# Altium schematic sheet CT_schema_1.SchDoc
size 385 x 337 mm
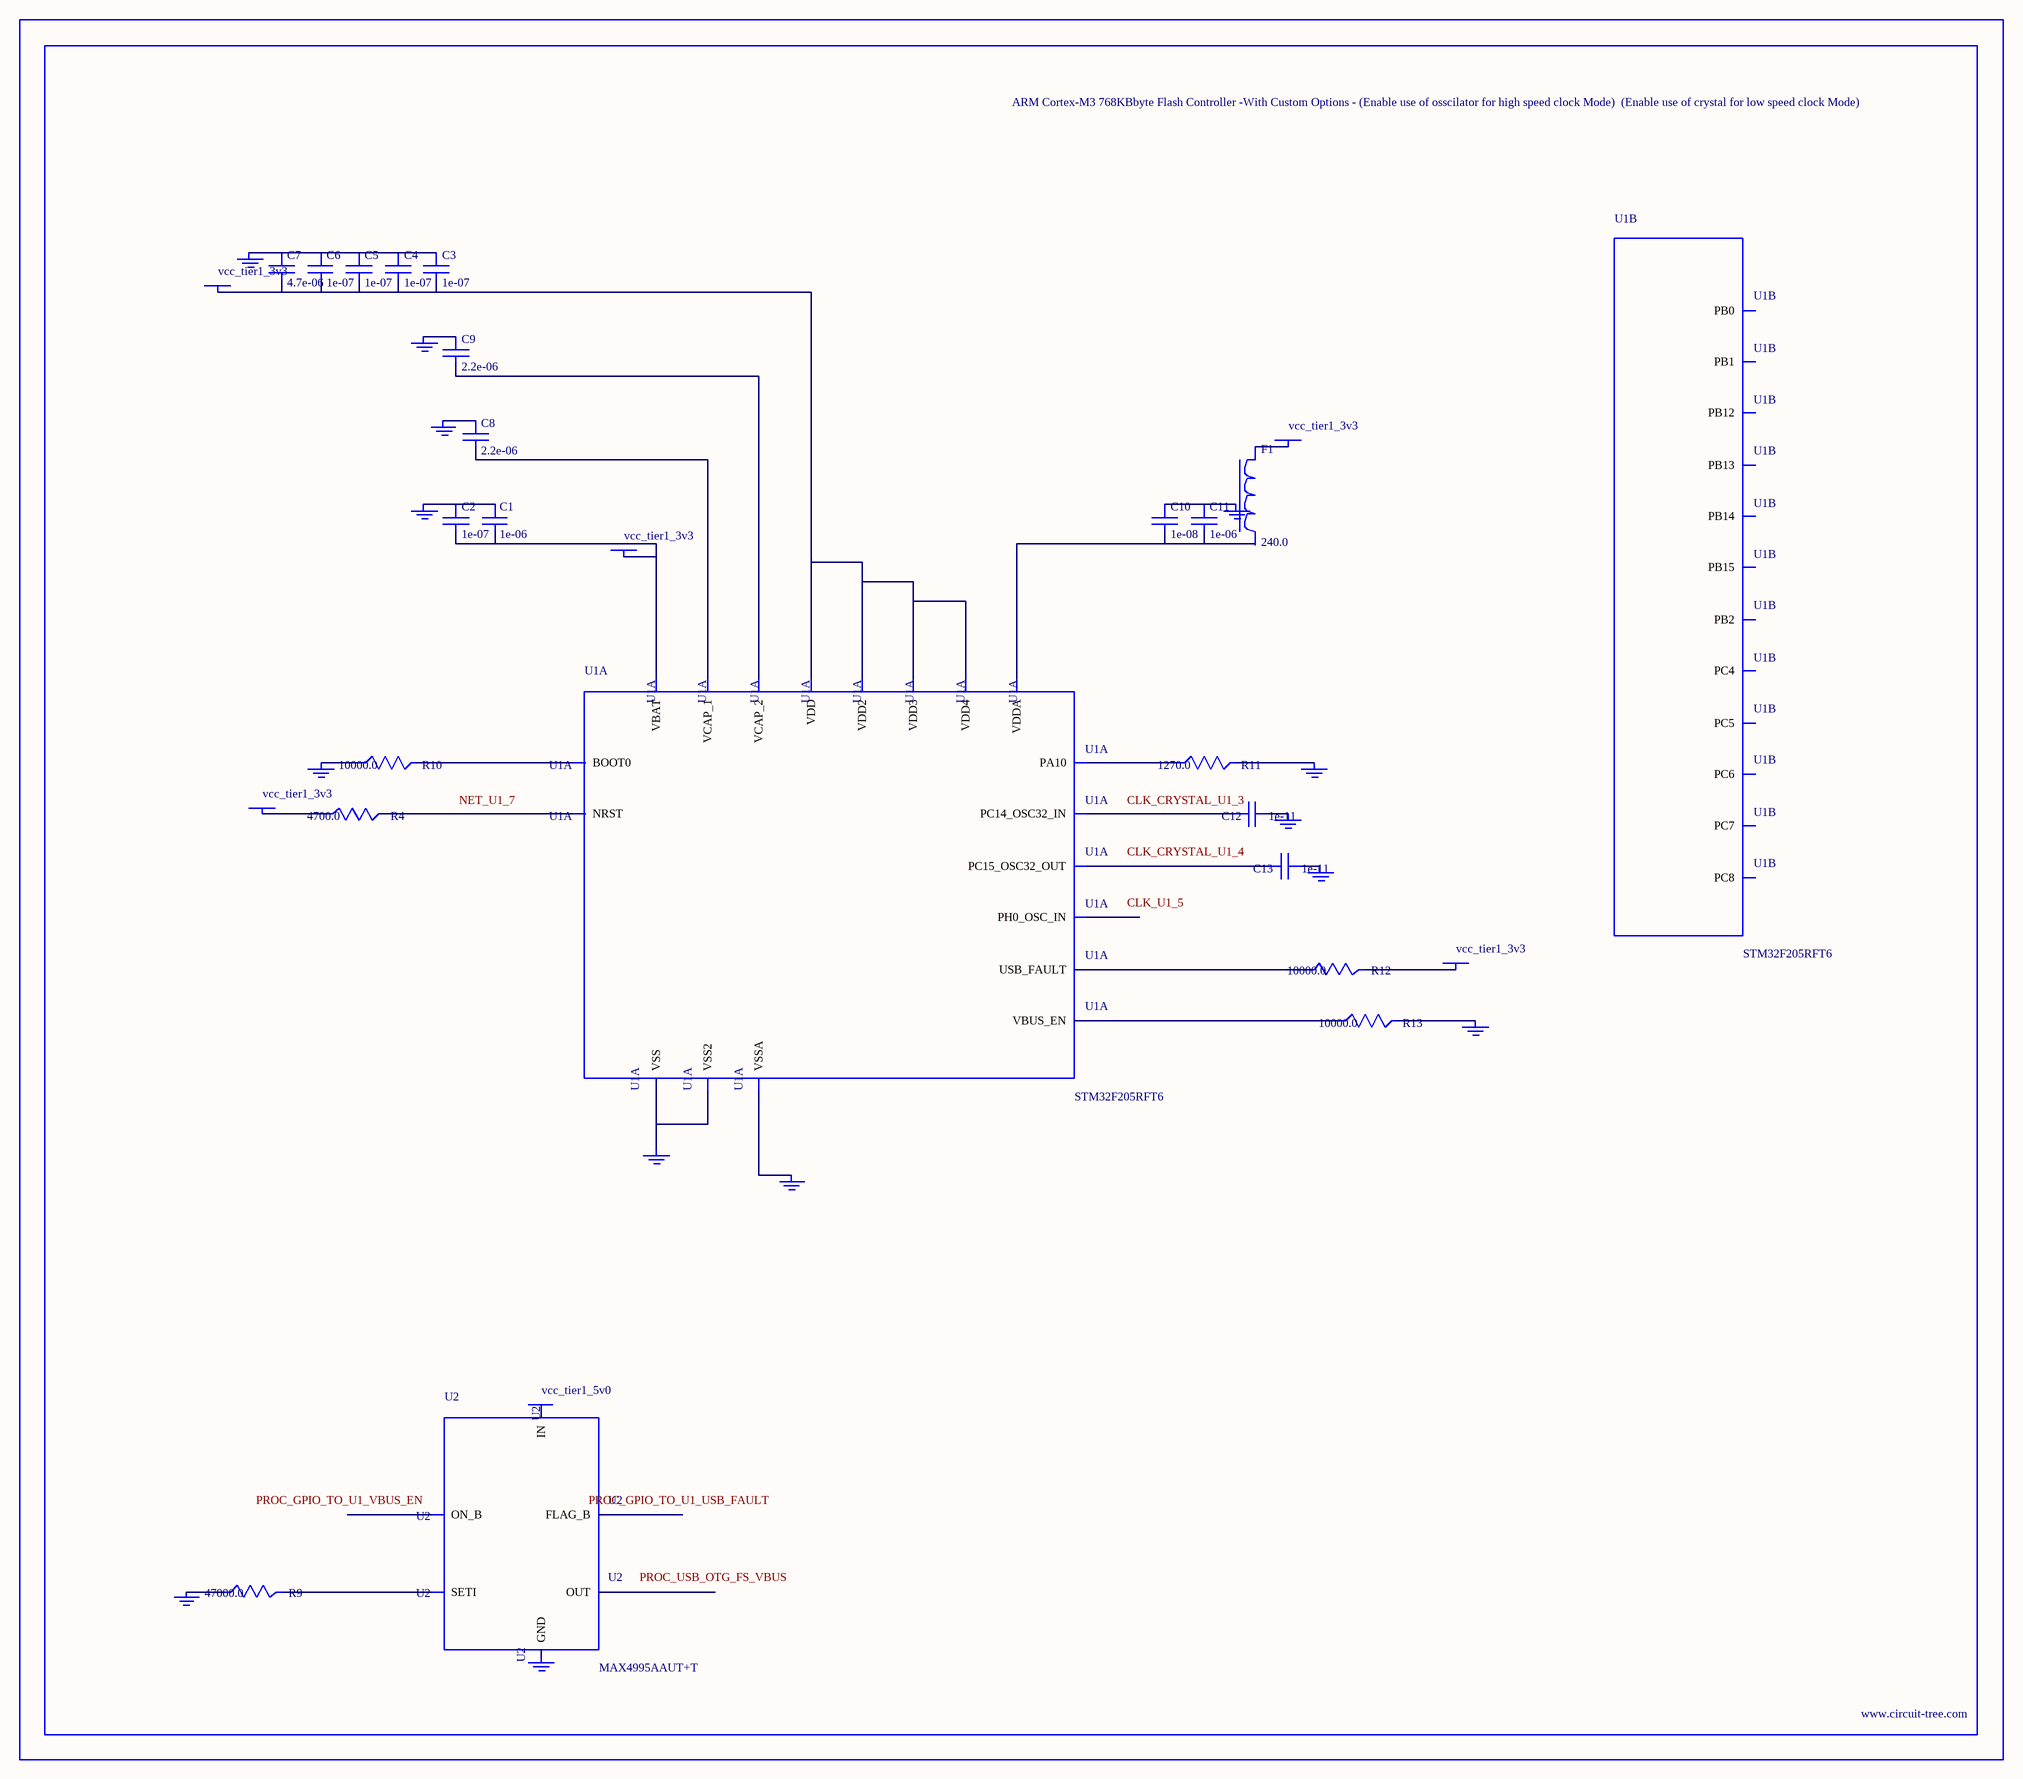
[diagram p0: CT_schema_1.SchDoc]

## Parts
BORDER0  (no value)
C1  1e-06  [C0603]
C2  1e-07  [C0603]
C3  1e-07  [C0603]
C4  1e-07  [C0603]
C5  1e-07  [C0603]
C6  1e-07  [C0603]
C7  4.7e-06  [C0603]
C8  2.2e-06  [C0603]
C9  2.2e-06  [C0603]
C10  1e-08  [C0603]
C11  1e-06  [C0603]
C12  1e-11  [C0402]
C13  1e-11  [C0402]
F1  240.0  [L0603]
GND_INSTANCE_0_0  (no value)
GND_INSTANCE_0_1  (no value)
GND_INSTANCE_0_2  (no value)
GND_INSTANCE_0_3  (no value)
GND_INSTANCE_0_4  (no value)
GND_INSTANCE_0_5  (no value)
GND_INSTANCE_0_6  (no value)
GND_INSTANCE_0_7  (no value)
GND_INSTANCE_0_8  (no value)
GND_INSTANCE_0_9  (no value)
GND_INSTANCE_0_10  (no value)
GND_INSTANCE_0_11  (no value)
GND_INSTANCE_0_12  (no value)
GND_INSTANCE_0_13  (no value)
POWER_INSTANCE_0_0  vcc_tier1_3v3
POWER_INSTANCE_0_1  vcc_tier1_3v3
POWER_INSTANCE_0_2  vcc_tier1_3v3
POWER_INSTANCE_0_3  vcc_tier1_3v3
POWER_INSTANCE_0_4  vcc_tier1_3v3
POWER_INSTANCE_0_5  vcc_tier1_5v0
R4  4700.0  [R0603]
R9  47000.0  [R0603]
R10  10000.0  [R0603]
R11  1270.0  [R0603]
R12  10000.0  [R0603]
R13  10000.0  [R0603]
U1  STM32F205RFT6  [LQFP64]  (parts A,B of 7)
U2  MAX4995AAUT+T  [SOT-23-6]

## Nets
NetC1_1: C1.1 C2.1 GND_INSTANCE_0_0.0(GND)
NetC1_2: C1.2 C2.2 POWER_INSTANCE_0_0.0(PWR) U1.1(VBAT)
NetC3_1: C3.1 C4.1 C5.1 C6.1 C7.1 GND_INSTANCE_0_6.0(GND)
NetC3_2: C3.2 C4.2 C5.2 C6.2 C7.2 POWER_INSTANCE_0_3.0(PWR) U1.19(VDD) U1.32(VDD2) U1.48(VDD3) U1.64(VDD4)
NetC8_1: C8.1 GND_INSTANCE_0_7.0(GND)
NetC8_2: C8.2 U1.31(VCAP_1)
NetC9_1: C9.1 GND_INSTANCE_0_9.0(GND)
NetC9_2: C9.2 U1.47(VCAP_2)
NetC10_1: C10.1 C11.1 GND_INSTANCE_0_5.0(GND)
NetC10_2: C10.2 C11.2 U1.13(VDDA)
NetC12_1: C12.1 GND_INSTANCE_0_2.0(GND)
NetC12_2: C12.2 U1.3(PC14_OSC32_IN)
NetC13_1: C13.1 GND_INSTANCE_0_3.0(GND)
NetC13_2: C13.2 U1.4(PC15_OSC32_OUT)
NetF1_1: F1.1 POWER_INSTANCE_0_2.0(PWR)
NetGND_INSTANCE_0_1_0: GND_INSTANCE_0_1.0(GND) R13.2
NetGND_INSTANCE_0_4_0: GND_INSTANCE_0_4.0(GND) U1.12(VSSA)
NetGND_INSTANCE_0_8_0: GND_INSTANCE_0_8.0(GND) R11.2
NetGND_INSTANCE_0_10_0: GND_INSTANCE_0_10.0(GND) R10.1
NetGND_INSTANCE_0_11_0: GND_INSTANCE_0_11.0(GND) U1.18(VSS) U1.63(VSS2)
NetGND_INSTANCE_0_12_0: GND_INSTANCE_0_12.0(GND) R9.1
NetPOWER_INSTANCE_0_1_0: POWER_INSTANCE_0_1.0(PWR) R12.2
NetPOWER_INSTANCE_0_4_0: POWER_INSTANCE_0_4.0(PWR) R4.1
NetR4_2: R4.2 U1.7(NRST)
NetR9_2: R9.2 U2.3(SETI)
NetR10_2: R10.2 U1.60(BOOT0)
NetR11_1: R11.1 U1.43(PA10)
NetR12_1: R12.1 U1.6(USB_FAULT)
NetR13_1: R13.1 U1.2(VBUS_EN)

Not connected (* = marked no-connect by the designer): F1 2; GND_INSTANCE_0_13 0(GND); POWER_INSTANCE_0_5 0(PWR); U1 5(PH0_OSC_IN) 24(PC4) 25(PC5) 26(PB0) 27(PB1) 28(PB2) 33(PB12) 34(PB13) 35(PB14) 36(PB15) 37(PC6) 38(PC7) 39(PC8); U2 1(OUT) 2(GND) 4(ON_B) 5(IN) 6(FLAG_B)

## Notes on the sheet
- Labels drawn without touching a wire or pin: CLK_CRYSTAL_U1_3, CLK_CRYSTAL_U1_4, CLK_U1_5, NET_U1_7, PROC_GPIO_TO_U1_USB_FAULT, PROC_GPIO_TO_U1_VBUS_EN, PROC_USB_OTG_FS_VBUS

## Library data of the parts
BORDER0 = BORDER_PAGE0
C1 C11 = C0603C105K3RACTU
C2-C6 = 06035C104K4Z2A
C7 = GRM188R6YA475KE15D
C8 C9 = C0603C225K8RACTU
C10 = 06035C103K4Z2A
C12 C13 = C0402C100K3GACTU
F1 = Z0603C241ASMST
GND_INSTANCE_0_0-GND_INSTANCE_0_13 = GND
POWER_INSTANCE_0_0-POWER_INSTANCE_0_5 = PWR
R4 = RC0603JR-074K7L
R9 = RC0603JR-0747KL
R10 R12 R13 = RC0603JR-0710KL
R11 = RC0603FR-071K27L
